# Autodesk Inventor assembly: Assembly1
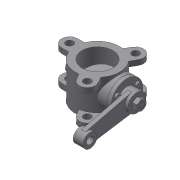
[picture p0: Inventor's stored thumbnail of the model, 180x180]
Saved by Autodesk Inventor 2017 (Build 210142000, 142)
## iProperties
Created: 2016-07
Part Number: Assembly1
Document SubType Name: Assembly
Designer: Sandeep
Author: Sandeep
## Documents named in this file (9)
- D:\KAVITA\Autodesk Inventor_2017_Project\Part's File\Inventor_2016_tut\c10_Inv_tut_2016\c10_tut01_inv\Butterfly Valve\Assembly1.iam
- D:\KAVITA\Autodesk Inventor_2017_Project\Part's File\Inventor_2016_tut\c10_Inv_tut_2016\c10_tut01_inv\Butterfly Valve\Body.ipt
- D:\KAVITA\Autodesk Inventor_2017_Project\Part's File\Inventor_2016_tut\c10_Inv_tut_2016\c10_tut01_inv\Butterfly Valve\shaft1.ipt
- D:\KAVITA\Autodesk Inventor_2017_Project\Part's File\Inventor_2016_tut\c10_Inv_tut_2016\c10_tut01_inv\Butterfly Valve\Arm1.ipt
- D:\KAVITA\Autodesk Inventor_2017_Project\Part's File\Inventor_2016_tut\c10_Inv_tut_2016\c10_tut01_inv\Butterfly Valve\Retainer.ipt
- D:\KAVITA\Autodesk Inventor_2017_Project\Part's File\Inventor_2016_tut\c10_Inv_tut_2016\c10_tut01_inv\Butterfly Valve\scew1.ipt
- D:\KAVITA\Autodesk Inventor_2017_Project\Part's File\Inventor_2016_tut\c10_Inv_tut_2016\c10_tut01_inv\Butterfly Valve\Plate.ipt
- D:\KAVITA\Autodesk Inventor_2017_Project\Part's File\Inventor_2016_tut\c10_Inv_tut_2016\c10_tut01_inv\Butterfly Valve\Screw.ipt
- D:\KAVITA\Autodesk Inventor_2017_Project\Part's File\Inventor_2016_tut\c10_Inv_tut_2016\c10_tut01_inv\Butterfly Valve\Nut.ipt
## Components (11 placed, 8 different names)
1. Body:2 — Mate:1, Insert:2, Insert:3, Angle:3, Insert:12
2. shaft1:1 — Angle:2, Angle:3, Insert:5, Insert:6, Insert:12, Insert:13
3. Retainer:1 — Mate:1, Insert:2, Insert:3, Insert:4, Angle:1, Insert:14
4. Arm1:2 — Insert:4, Angle:1, Angle:2
5. scew1:1 — Insert:7
6. scew1:2 — Insert:8
7. Plate:1 — Insert:5, Insert:6, Insert:7, Insert:8
8. Nut:1 — Insert:13
9. Screw:1 — Insert:14
10. Screw:2
11. Screw:3
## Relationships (14: Insert 10, Angle 3, Mate 1)
- Mate:1: Body:2 ↔ Retainer:1
- Insert:2: Body:2 ↔ Retainer:1
- Insert:3: Body:2 ↔ Retainer:1
- Insert:4: Retainer:1 ↔ Arm1:2
- Angle:1: Retainer:1 ↔ Arm1:2
- Angle:2: shaft1:1 ↔ Arm1:2
- Angle:3: Body:2 ↔ shaft1:1
- Insert:5: shaft1:1 ↔ Plate:1
- Insert:6: shaft1:1 ↔ Plate:1
- Insert:7: scew1:1 ↔ Plate:1
- Insert:8: scew1:2 ↔ Plate:1
- Insert:12: Body:2 ↔ shaft1:1
- Insert:13: shaft1:1 ↔ Nut:1
- Insert:14: Retainer:1 ↔ Screw:1
